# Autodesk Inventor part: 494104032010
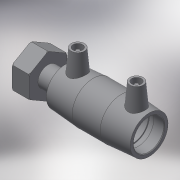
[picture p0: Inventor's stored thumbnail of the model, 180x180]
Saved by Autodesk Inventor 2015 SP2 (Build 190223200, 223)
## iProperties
Created: 2017-06
Part Number: 494104032010
Material: Generic
Description: PLASSON FEMALE FREE NUT TRANSITION COUPLER 32-1"
Document SubType Name: Modeling
Designer: KIM
Mass: 55.0731 g
Surface Area: 148.067 cm^2
Volume: 55.0731 cm^3
Density: 1 g/cm^3
Appearance: Default
Author: KIM
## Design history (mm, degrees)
derived "494104.ipt"
feature "Solid1::494104.ipt"
tag "TaggingFeature1"
body "Solid1"
other parameters: "d0" = 88, "d1" = 32, "d2" = 44, "d3" = 42, "d4" = 29.33333, "d5" = 39.6, "d6" = 30.4, "d7" = 32, "d8" = 168 deg, "d10" = 16.8, "d11" = 5.6, "d29" = 42, "d30" = 14, "d31" = 30.8, "d34" = 5 deg, "d41" = 4, "d42" = 14, "d43" = 0, "d48" = 3, "d49" = 0, "d55" = 36, "d57" = 19, "d80" = 0.64, "d83" = 18, "d84" = 11.88, "d85" = 1.188, "d86" = 24.2328, "d87" = 30.291, "d88" = 45.4365, "d89" = 44, "d90" = 0.90873, "d94" = 0, "d95" = 1.188, "d96" = 21.2037, "d_" = 32, "L_" = 124, "L_1" = 42, "D_1" = 44, "A_" = 42, "d_2" = 12, "L_2" = 36, "D_" = 19, "G_" = 30.291
